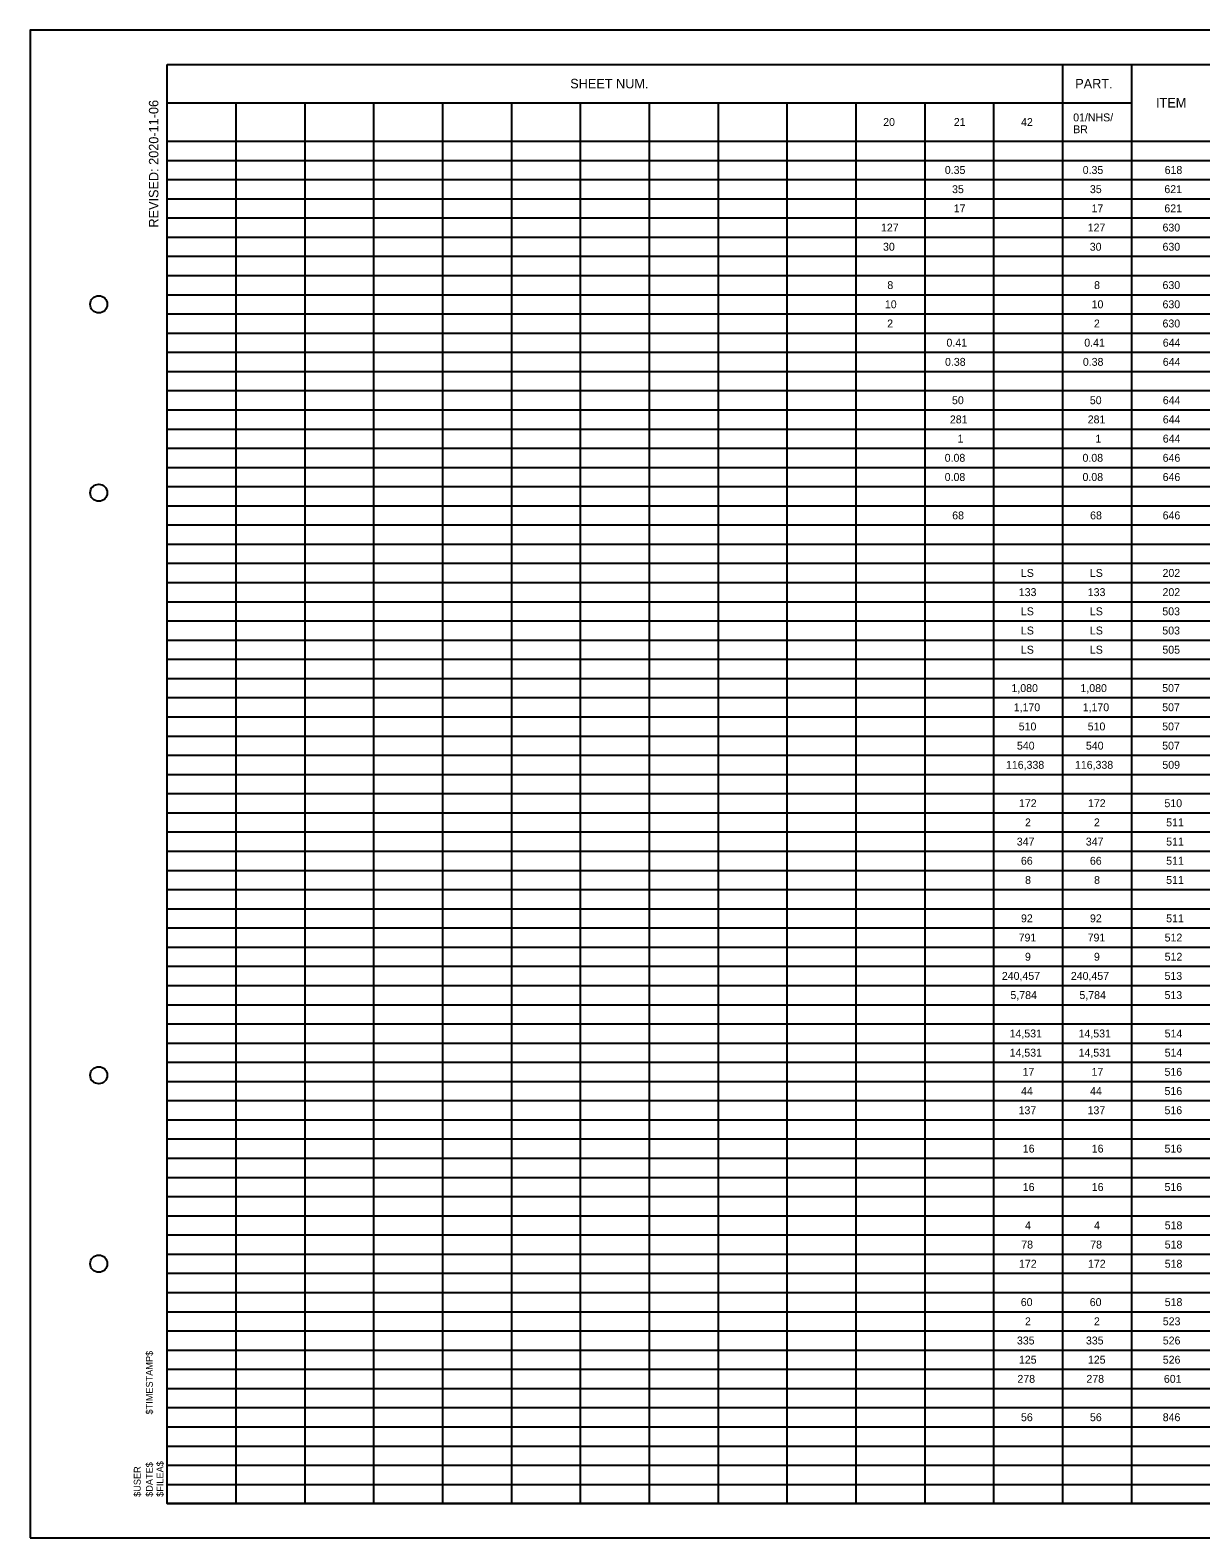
# Model space of a CAD drawing. Extents: x 0 to 34, y 0 to 22.
# Drawn here: x 0 to 17.07, y 0 to 22 of the extents above; entities that cross this region are included whole.
import ezdxf

# ---------------------------------------------------------------- set-up
doc = ezdxf.new("R2010")
doc.units = 0
for name, color, linetype in [('SH_Border', 7, 'Continuous'), ('SH_Cut_Line', 7, 'Continuous'), ('SH_Data', 7, 'Continuous'), ('SH_Text', 7, 'Continuous')]:
    doc.layers.add(name, color=color, linetype=linetype)

msp = doc.modelspace()

# ---------------------------------------------------------------- linework, layer by layer
at = {"layer": 'SH_Border'}
msp.add_lwpolyline([(2, 21.5), (33.5, 21.5), (33.5, 0.5), (2, 0.5)], close=True, dxfattribs=at)
for centre in [(1, 18), (1, 15.25), (1, 6.75), (1, 4)]:
    msp.add_circle(centre, 0.125, dxfattribs=at)
at = {"layer": 'SH_Cut_Line'}
msp.add_lwpolyline([(0, 0), (34, 0), (34, 22), (0, 22)], close=True, dxfattribs=at)
at = {"layer": 'SH_Text'}
for p, q in [((2, 21.5), (2, 21.5)), ((2, 21.5), (32.5, 21.5)), ((2, 0.5), (2, 21.5)), ((15.06, 0.5), (15.06, 21.5)), ((16.064, 0.5), (16.064, 21.5)), ((2, 20.94), (16.064, 20.94)), ((3.005, 0.5), (3.005, 20.94)), ((4.009, 0.5), (4.009, 20.94)), ((5.014, 0.5), (5.014, 20.94)), ((6.018, 0.5), (6.018, 20.94)), ((7.023, 0.5), (7.023, 20.94)), ((8.028, 0.5), (8.028, 20.94)), ((9.032, 0.5), (9.032, 20.94)), ((10.037, 0.5), (10.037, 20.94)), ((11.041, 0.5), (11.041, 20.94)), ((12.046, 0.5), (12.046, 20.94)), ((13.05, 0.5), (13.05, 20.94)), ((14.055, 0.5), (14.055, 20.94)), ((2, 20.38), (15.06, 20.38)), ((14.055, 20.38), (32.5, 20.38)), ((2, 20.1), (32.5, 20.1)), ((2, 19.82), (32.5, 19.82)), ((2, 19.54), (32.5, 19.54)), ((2, 19.26), (32.5, 19.26)), ((2, 18.98), (32.5, 18.98)), ((2, 18.7), (32.5, 18.7)), ((2, 18.42), (32.5, 18.42)), ((2, 18.14), (32.5, 18.14)), ((2, 17.86), (32.5, 17.86)), ((2, 17.58), (32.5, 17.58)), ((2, 17.3), (32.5, 17.3)), ((2, 17.02), (32.5, 17.02)), ((2, 16.74), (32.5, 16.74)), ((2, 16.46), (32.5, 16.46)), ((2, 16.18), (32.5, 16.18)), ((2, 15.9), (32.5, 15.9)), ((2, 15.62), (32.5, 15.62)), ((2, 15.34), (32.5, 15.34)), ((2, 15.06), (32.5, 15.06)), ((2, 14.78), (32.5, 14.78)), ((2, 14.5), (32.5, 14.5)), ((2, 14.22), (32.5, 14.22)), ((2, 13.94), (32.5, 13.94)), ((2, 13.66), (32.5, 13.66)), ((2, 13.38), (32.5, 13.38)), ((2, 13.1), (32.5, 13.1)), ((2, 12.82), (32.5, 12.82)), ((2, 12.54), (32.5, 12.54)), ((2, 12.26), (32.5, 12.26)), ((2, 11.98), (32.5, 11.98)), ((2, 11.7), (32.5, 11.7)), ((2, 11.42), (32.5, 11.42)), ((2, 11.14), (32.5, 11.14)), ((2, 10.86), (32.5, 10.86)), ((2, 10.58), (32.5, 10.58)), ((2, 10.3), (32.5, 10.3)), ((2, 10.02), (32.5, 10.02)), ((2, 9.74), (32.5, 9.74)), ((2, 9.46), (32.5, 9.46)), ((2, 9.18), (32.5, 9.18)), ((2, 8.9), (32.5, 8.9)), ((2, 8.62), (32.5, 8.62)), ((2, 8.34), (32.5, 8.34)), ((2, 8.06), (32.5, 8.06)), ((2, 7.78), (32.5, 7.78)), ((2, 7.5), (32.5, 7.5)), ((2, 7.22), (32.5, 7.22)), ((2, 6.94), (32.5, 6.94)), ((2, 6.66), (32.5, 6.66)), ((2, 6.38), (32.5, 6.38)), ((2, 6.1), (32.5, 6.1)), ((2, 5.82), (32.5, 5.82)), ((2, 5.54), (32.5, 5.54)), ((2, 5.26), (32.5, 5.26)), ((2, 4.98), (32.5, 4.98)), ((2, 4.7), (32.5, 4.7)), ((2, 4.42), (32.5, 4.42)), ((2, 4.14), (32.5, 4.14)), ((2, 3.86), (32.5, 3.86)), ((2, 3.58), (32.5, 3.58)), ((2, 3.3), (32.5, 3.3)), ((2, 3.02), (32.5, 3.02)), ((2, 2.74), (32.5, 2.74)), ((2, 2.46), (32.5, 2.46)), ((2, 2.18), (32.5, 2.18)), ((2, 1.9), (32.5, 1.9)), ((2, 1.62), (32.5, 1.62)), ((2, 1.34), (32.5, 1.34)), ((2, 1.06), (32.5, 1.06)), ((2, 0.78), (32.5, 0.78)), ((2, 0.5), (32.5, 0.5))]:
    msp.add_line(p, q, dxfattribs=at)

# ---------------------------------------------------------------- texts
at = {"layer": 'SH_Data'}
for s, p in [('$TIMESTAMP$', (1.788, 1.8)), ('$DATE$', (1.788, 0.598)), ('$FILEA$', (1.944, 0.598)), ('$USER', (1.611, 0.598))]:
    msp.add_text(s, height=0.1, rotation=89.9931, dxfattribs=at).set_placement(p)
at = {"layer": 'SH_Text'}
for s, height, p in [('SHEET NUM.', 0.1384, (7.876, 21.151)), ('PART.', 0.1384, (15.241, 21.151)), ('ITEM', 0.1384, (16.419, 20.871)), ('20', 0.1153, (12.44, 20.602)), ('21', 0.1153, (13.47, 20.602)), ('42', 0.1153, (14.451, 20.602)), ('01/NHS/', 0.1153, (15.211, 20.669)), ('BR', 0.1153, (15.211, 20.496)), ('0.35', 0.1153, (13.339, 19.902)), ('0.35', 0.1153, (15.35, 19.902)), ('618', 0.1153, (16.545, 19.902)), ('35', 0.1153, (13.445, 19.622)), ('35', 0.1153, (15.455, 19.622)), ('621', 0.1153, (16.541, 19.622)), ('17', 0.1153, (13.469, 19.342)), ('17', 0.1153, (15.479, 19.342)), ('621', 0.1153, (16.541, 19.342)), ('127', 0.1153, (12.408, 19.062)), ('127', 0.1153, (15.423, 19.062)), ('630', 0.1153, (16.514, 19.062)), ('30', 0.1153, (12.438, 18.782)), ('30', 0.1153, (15.453, 18.782)), ('630', 0.1153, (16.514, 18.782)), ('8', 0.115, (12.501, 18.222)), ('8', 0.115, (15.516, 18.222)), ('630', 0.1153, (16.514, 18.222)), ('10', 0.1153, (12.465, 17.942)), ('10', 0.1153, (15.48, 17.942)), ('630', 0.1153, (16.514, 17.942)), ('2', 0.115, (12.499, 17.662)), ('2', 0.115, (15.514, 17.662)), ('630', 0.1153, (16.514, 17.662)), ('0.41', 0.1153, (13.363, 17.382)), ('0.41', 0.1153, (15.373, 17.382)), ('644', 0.1153, (16.518, 17.382)), ('0.38', 0.1153, (13.342, 17.102)), ('0.38', 0.1153, (15.352, 17.102)), ('644', 0.1153, (16.518, 17.102)), ('50', 0.1153, (13.444, 16.542)), ('50', 0.1153, (15.454, 16.542)), ('644', 0.1153, (16.518, 16.542)), ('281', 0.1153, (13.413, 16.262)), ('281', 0.1153, (15.423, 16.262)), ('644', 0.1153, (16.518, 16.262)), ('1', 0.115, (13.525, 15.982)), ('1', 0.115, (15.536, 15.982)), ('644', 0.1153, (16.518, 15.982)), ('0.08', 0.1153, (13.337, 15.702)), ('0.08', 0.1153, (15.347, 15.702)), ('646', 0.1153, (16.516, 15.702)), ('0.08', 0.1153, (13.337, 15.422)), ('0.08', 0.1153, (15.347, 15.422)), ('646', 0.1153, (16.516, 15.422)), ('68', 0.1153, (13.447, 14.862)), ('68', 0.1153, (15.458, 14.862)), ('646', 0.1153, (16.516, 14.862)), ('LS', 0.1153, (14.449, 14.022)), ('LS', 0.1153, (15.455, 14.022)), ('202', 0.1153, (16.514, 14.022)), ('133', 0.1153, (14.418, 13.742)), ('133', 0.1153, (15.424, 13.742)), ('202', 0.1153, (16.514, 13.742)), ('LS', 0.1153, (14.449, 13.462)), ('LS', 0.1153, (15.455, 13.462)), ('503', 0.1153, (16.511, 13.462)), ('LS', 0.1153, (14.449, 13.182)), ('LS', 0.1153, (15.455, 13.182)), ('503', 0.1153, (16.511, 13.182)), ('LS', 0.1153, (14.449, 12.902)), ('LS', 0.1153, (15.455, 12.902)), ('505', 0.1153, (16.512, 12.902)), ('1,080', 0.1153, (14.311, 12.342)), ('1,080', 0.1153, (15.317, 12.342)), ('507', 0.1153, (16.509, 12.342)), ('1,170', 0.1153, (14.344, 12.062)), ('1,170', 0.1153, (15.35, 12.062)), ('507', 0.1153, (16.509, 12.062)), ('510', 0.1153, (14.417, 11.782)), ('510', 0.1153, (15.423, 11.782)), ('507', 0.1153, (16.509, 11.782)), ('540', 0.1153, (14.391, 11.502)), ('540', 0.1153, (15.397, 11.502)), ('507', 0.1153, (16.509, 11.502)), ('116,338', 0.1153, (14.231, 11.222)), ('116,338', 0.1153, (15.237, 11.222)), ('509', 0.1153, (16.512, 11.222)), ('172', 0.1153, (14.421, 10.662)), ('172', 0.1153, (15.427, 10.662)), ('510', 0.1153, (16.542, 10.662)), ('2', 0.115, (14.508, 10.382)), ('2', 0.115, (15.514, 10.382)), ('511', 0.1153, (16.567, 10.382)), ('347', 0.1153, (14.389, 10.102)), ('347', 0.1153, (15.395, 10.102)), ('511', 0.1153, (16.567, 10.102)), ('66', 0.1153, (14.449, 9.822)), ('66', 0.1153, (15.455, 9.822)), ('511', 0.1153, (16.567, 9.822)), ('8', 0.115, (14.51, 9.542)), ('8', 0.115, (15.516, 9.542)), ('511', 0.1153, (16.567, 9.542)), ('92', 0.1153, (14.45, 8.982)), ('92', 0.1153, (15.456, 8.982)), ('511', 0.1153, (16.567, 8.982)), ('791', 0.1153, (14.416, 8.702)), ('791', 0.1153, (15.422, 8.702)), ('512', 0.1153, (16.545, 8.702)), ('9', 0.115, (14.508, 8.422)), ('9', 0.115, (15.514, 8.422)), ('512', 0.1153, (16.545, 8.422)), ('240,457', 0.1153, (14.171, 8.142)), ('240,457', 0.1153, (15.177, 8.142)), ('513', 0.1153, (16.543, 8.142)), ('5,784', 0.1153, (14.296, 7.862)), ('5,784', 0.1153, (15.302, 7.862)), ('513', 0.1153, (16.543, 7.862)), ('14,531', 0.1153, (14.284, 7.302)), ('14,531', 0.1153, (15.29, 7.302)), ('514', 0.1153, (16.545, 7.302)), ('14,531', 0.1153, (14.284, 7.022)), ('14,531', 0.1153, (15.29, 7.022)), ('514', 0.1153, (16.545, 7.022)), ('17', 0.1153, (14.473, 6.742)), ('17', 0.1153, (15.479, 6.742)), ('516', 0.1153, (16.543, 6.742)), ('44', 0.1153, (14.451, 6.462)), ('44', 0.1153, (15.457, 6.462)), ('516', 0.1153, (16.543, 6.462)), ('137', 0.1153, (14.415, 6.182)), ('137', 0.1153, (15.421, 6.182)), ('516', 0.1153, (16.543, 6.182)), ('16', 0.1153, (14.476, 5.622)), ('16', 0.1153, (15.482, 5.622)), ('516', 0.1153, (16.543, 5.622)), ('16', 0.1153, (14.476, 5.062)), ('16', 0.1153, (15.482, 5.062)), ('516', 0.1153, (16.543, 5.062)), ('4', 0.115, (14.509, 4.502)), ('4', 0.115, (15.515, 4.502)), ('518', 0.1153, (16.546, 4.502)), ('78', 0.1153, (14.454, 4.222)), ('78', 0.1153, (15.46, 4.222)), ('518', 0.1153, (16.546, 4.222)), ('172', 0.1153, (14.421, 3.942)), ('172', 0.1153, (15.427, 3.942)), ('518', 0.1153, (16.546, 3.942)), ('60', 0.1153, (14.447, 3.382)), ('60', 0.1153, (15.453, 3.382)), ('518', 0.1153, (16.546, 3.382)), ('2', 0.115, (14.508, 3.102)), ('2', 0.115, (15.514, 3.102)), ('523', 0.1153, (16.518, 3.102)), ('335', 0.1153, (14.391, 2.822)), ('335', 0.1153, (15.397, 2.822)), ('526', 0.1153, (16.518, 2.822)), ('125', 0.1153, (14.42, 2.542)), ('125', 0.1153, (15.426, 2.542)), ('526', 0.1153, (16.518, 2.542)), ('278', 0.1153, (14.398, 2.262)), ('278', 0.1153, (15.404, 2.262)), ('601', 0.1153, (16.534, 2.262)), ('56', 0.1153, (14.45, 1.702)), ('56', 0.1153, (15.456, 1.702)), ('846', 0.1153, (16.517, 1.702))]:
    msp.add_text(s, height=height, dxfattribs=at).set_placement(p)
msp.add_text('REVISED: 2020-11-06', height=0.13841, rotation=90, dxfattribs=at).set_placement((1.87, 19.119))

doc.saveas('drawing.dxf')
